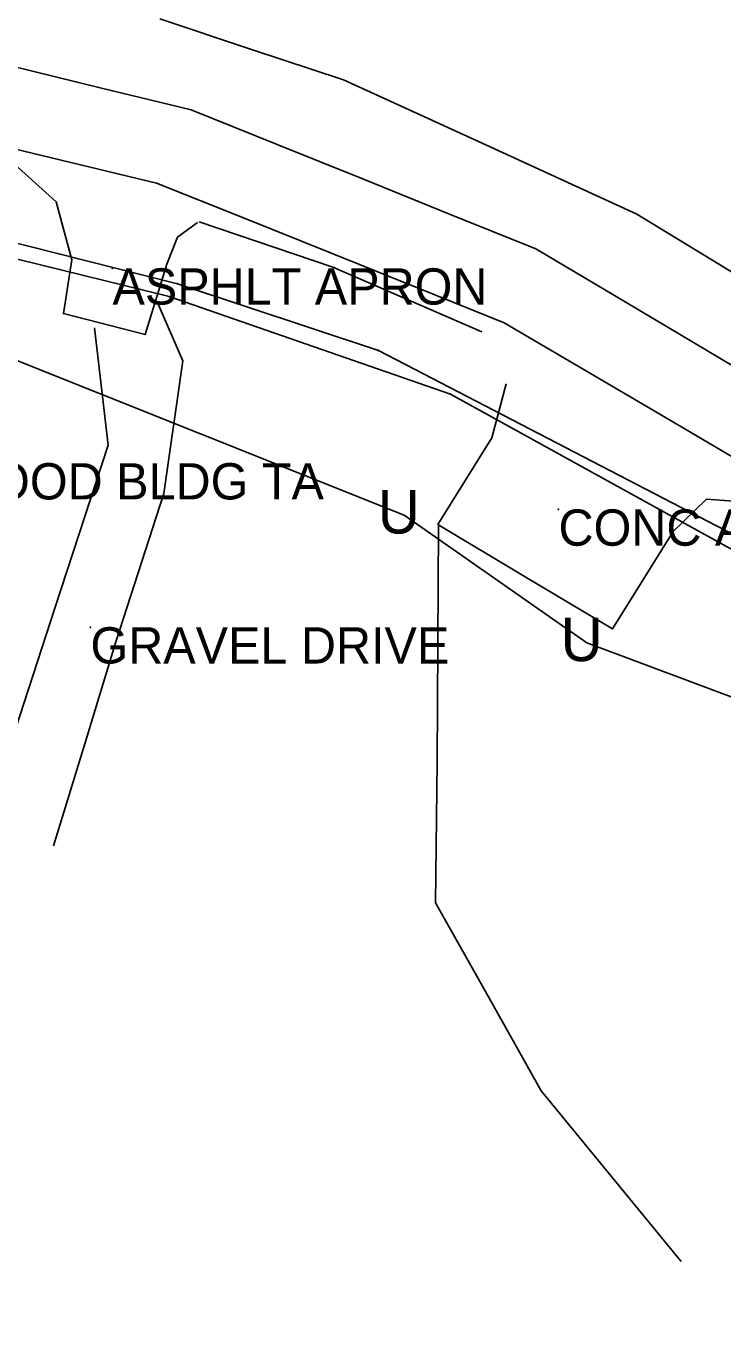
# Model space of a CAD drawing. Extents: x 1050807 to 1053552, y 395828 to 398415.
# Drawn here: x 1051813.5 to 1051909.5, y 397889.3 to 398068.8 of the extents above; entities that cross this region are included whole.
import ezdxf

# ---------------------------------------------------------------- set-up
doc = ezdxf.new("R2010")
doc.units = 0
for name, color, linetype in [('Default', 7, 'Continuous'), ('S_BUILDING_ANNOT', 7, 'Continuous'), ('S_DRIVEWAY', 7, 'Continuous'), ('S_EDGE_PAVEMENT', 7, 'Continuous'), ('S_GRAVEL_ROAD', 7, 'Continuous'), ('S_MSC_PT_SYM', 7, 'Continuous'), ('S_PAVEMENT_CROWN', 7, 'Continuous'), ('S_SHOULDER', 7, 'Continuous'), ('S_SURVEY_TEXT_ANNOT', 7, 'Continuous'), ('S_UNDERGROUND_CABLE', 7, 'Continuous'), ('S_UTL_PT_SYM', 7, 'Continuous'), ('S_WATER_UTILITIES', 7, 'Continuous')]:
    doc.layers.add(name, color=color, linetype=linetype)

msp = doc.modelspace()

# ---------------------------------------------------------------- linework, layer by layer
at = {"layer": 'S_DRIVEWAY'}
for points in [[(1051817.31, 397955.74), (1051821.6, 397969.8), (1051825.88, 397983.86), (1051832.49, 398004.3), (1051835.12, 398022.62), (1051831.59, 398030.75)], [(1051822.94, 398027.14), (1051824.81, 398010.97), (1051817.54, 397988.65), (1051810.28, 397966.32), (1051806.07, 397951.84)]]:
    msp.add_lwpolyline(points, dxfattribs=at)
at = {"layer": 'S_EDGE_PAVEMENT'}
for points in [[(1052043.7, 397907.48), (1052036.23, 397917.81), (1052028.77, 397928.15), (1052021.31, 397938.48), (1052013.84, 397948.81), (1052004.91, 397958.24), (1051995.98, 397967.66), (1051987.04, 397977.09), (1051978.11, 397986.52), (1051960.19, 398001.02), (1051942.28, 398015.53), (1051931.11, 398022.36), (1051919.95, 398029.19), (1051908.79, 398036.02), (1051897.62, 398042.85), (1051877.43, 398052.09), (1051857.24, 398061.33), (1051844.58, 398065.54), (1051831.93, 398069.76)], [(1052038.69, 397873.19), (1052032.04, 397883.85), (1052025.39, 397894.51), (1052018.74, 397905.17), (1052012.09, 397915.83), (1052004.02, 397925.46), (1051995.95, 397935.08), (1051987.88, 397944.7), (1051979.81, 397954.32), (1051970.07, 397963.03), (1051960.33, 397971.74), (1051950.59, 397980.46), (1051940.85, 397989.17), (1051920.67, 398003.53), (1051900.02, 398015.7), (1051879.38, 398027.86), (1051867.4, 398032.67), (1051855.43, 398037.49), (1051843.45, 398042.3), (1051831.48, 398047.11), (1051807.63, 398052.86)], [(1051837.11, 398041.69), (1051834.35, 398039.68), (1051832.92, 398035.92), (1051829.91, 398026.23), (1051818.65, 398029.13), (1051819.81, 398036.54), (1051817.64, 398044.52), (1051811, 398050.54)]]:
    msp.add_lwpolyline(points, dxfattribs=at)
at = {"layer": 'S_GRAVEL_ROAD'}
for points in [[(1051907.23, 398003.55), (1051902.62, 397999.1), (1051894.29, 397985.64), (1051882.26, 397992.84), (1051870.22, 398000.04), (1051877.64, 398011.99), (1051879.61, 398019.44)], [(1051907.2, 398003.55), (1051915.88, 398002.91), (1051917.6, 397989.1), (1051925.25, 397976.64), (1051940.24, 397961.7), (1051955.22, 397946.76), (1051966.38, 397933.09), (1051977.54, 397919.42), (1051982.83, 397903.76), (1051988.12, 397888.11), (1051995.11, 397874.29), (1052002.09, 397860.47), (1052012.08, 397846.73), (1052024.66, 397838)], [(1051903.75, 397898.45), (1051894.11, 397910.21), (1051884.47, 397921.97), (1051877.19, 397934.94), (1051869.92, 397947.91), (1051870.13, 397967.34), (1051870.21, 397983.58), (1051870.3, 397999.81)]]:
    msp.add_lwpolyline(points, dxfattribs=at)
at = {"layer": 'S_MSC_PT_SYM'}
for points in [[(1051825.41, 398035.36), (1051825.41, 398035.41), (1051825.41, 398035.36), (1051825.36, 398035.36), (1051825.41, 398035.36), (1051825.41, 398035.31), (1051825.41, 398035.36), (1051825.46, 398035.36)], [(1051886.84, 398002.12), (1051886.84, 398002.17), (1051886.84, 398002.12), (1051886.79, 398002.12), (1051886.84, 398002.12), (1051886.84, 398002.07), (1051886.84, 398002.12), (1051886.89, 398002.12)], [(1051822.38, 397985.88), (1051822.38, 397985.93), (1051822.38, 397985.88), (1051822.33, 397985.88), (1051822.38, 397985.88), (1051822.38, 397985.83), (1051822.38, 397985.88), (1051822.43, 397985.88)]]:
    msp.add_lwpolyline(points, dxfattribs=at)
at = {"layer": 'S_PAVEMENT_CROWN'}
msp.add_lwpolyline([(1052041.36, 397889.37), (1052035.08, 397900.29), (1052028.8, 397911.2), (1052020.99, 397921.23), (1052013.18, 397931.25), (1052005.37, 397941.28), (1051997.56, 397951.3), (1051979.95, 397968.52), (1051962.34, 397985.74), (1051944.75, 397998.96), (1051927.16, 398012.19), (1051916.3, 398018.66), (1051905.43, 398025.13), (1051894.57, 398031.6), (1051883.71, 398038.07), (1051871.84, 398042.85), (1051859.97, 398047.63), (1051848.1, 398052.42), (1051836.23, 398057.2), (1051823.74, 398060.25), (1051811.24, 398063.31)], dxfattribs=at)
at = {"layer": 'S_SHOULDER'}
msp.add_lwpolyline([(1051876.26, 398026.62), (1051855.77, 398035.53), (1051837.33, 398041.76)], dxfattribs=at)
at = {"layer": 'S_UNDERGROUND_CABLE'}
for p, q in [((1051865.58, 398001.34), (1051771.74, 398038.8)), ((1051890.76, 397983.75), (1051865.58, 398001.34)), ((1051916.91, 397973.9), (1051890.76, 397983.75))]:
    msp.add_line(p, q, dxfattribs=at)
at = {"layer": 'S_UTL_PT_SYM'}
for points in [[(1051834.35, 398033.24), (1051834.35, 398033.29), (1051834.35, 398033.24), (1051834.3, 398033.24), (1051834.35, 398033.24), (1051834.35, 398033.19), (1051834.35, 398033.24), (1051834.4, 398033.24)], [(1051833.2, 398031.46), (1051833.2, 398031.51), (1051833.2, 398031.46), (1051833.15, 398031.46), (1051833.2, 398031.46), (1051833.2, 398031.41), (1051833.2, 398031.46), (1051833.25, 398031.46)], [(1051862.03, 398024.03), (1051862.03, 398024.08), (1051862.03, 398024.03), (1051861.98, 398024.03), (1051862.03, 398024.03), (1051862.03, 398023.98), (1051862.03, 398024.03), (1051862.08, 398024.03)], [(1051871.96, 398018.02), (1051871.96, 398018.07), (1051871.96, 398018.02), (1051871.91, 398018.02), (1051871.96, 398018.02), (1051871.96, 398017.97), (1051871.96, 398018.02), (1051872.01, 398018.02)]]:
    msp.add_lwpolyline(points, dxfattribs=at)
at = {"layer": 'S_WATER_UTILITIES'}
for p, q in [((1051834.35, 398033.24), (1051789.46, 398044.53)), ((1051833.2, 398031.46), (1051789.07, 398042.3)), ((1051862.03, 398024.03), (1051834.35, 398033.24)), ((1051871.96, 398018.02), (1051833.2, 398031.46)), ((1051924.71, 397991.46), (1051862.03, 398024.03)), ((1051923.28, 397989.65), (1051871.96, 398018.02))]:
    msp.add_line(p, q, dxfattribs=at)

# ---------------------------------------------------------------- texts
at = {"layer": 'Default'}
for p in [(1051861.95, 397998.8), (1051887.13, 397981.21)]:
    msp.add_text('U', height=6, dxfattribs=at).set_placement(p)
at = {"layer": 'S_BUILDING_ANNOT'}
msp.add_text('CONC BLK AND WOOD BLDG TA', height=5, dxfattribs=at).set_placement((1051750.51, 398003.5))
at = {"layer": 'S_SURVEY_TEXT_ANNOT'}
for s, p in [('ASPHLT APRON', (1051825.41, 398030.36)), ('CONC APRON', (1051886.84, 397997.12)), ('GRAVEL DRIVE', (1051822.38, 397980.88))]:
    msp.add_text(s, height=5, dxfattribs=at).set_placement(p)

doc.saveas('drawing.dxf')
